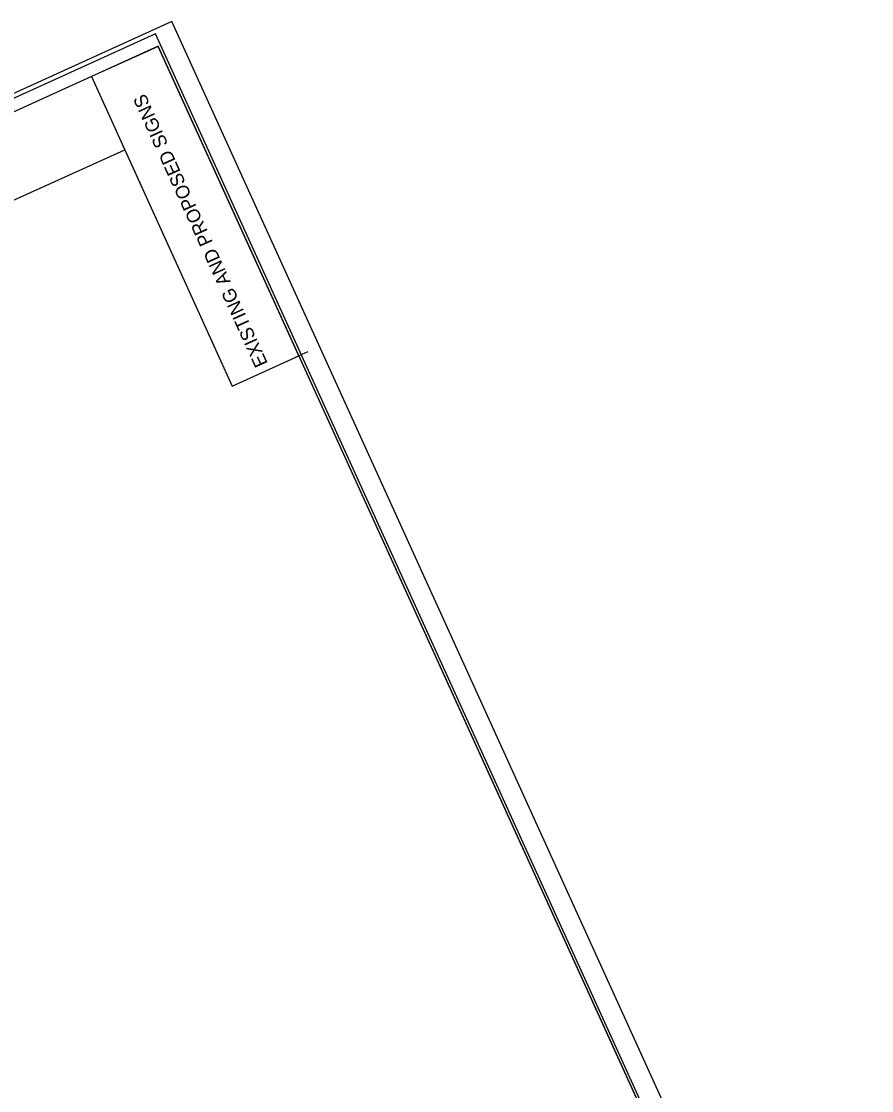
# Model space of a CAD drawing. Extents: x 2096093 to 2099001, y 683546 to 685907.
# Drawn here: x 2098154 to 2099001, y 684843 to 685907 of the extents above; entities that cross this region are included whole.
import ezdxf

# ---------------------------------------------------------------- set-up
doc = ezdxf.new("R2010")
doc.units = 0
for name, color, linetype in [('Default', 7, 'Continuous'), ('Old_Level_10', 7, 'Continuous'), ('Scratch_Level_0', 7, 'Continuous'), ('Scratch_Level_4', 7, 'Continuous'), ('Sheet Layout Plan Border', 7, 'Continuous'), ('Sheet Plan CELL', 7, 'Continuous'), ('Sheet Plot Border Inside CELL', 7, 'Continuous'), ('Sheet Plot Border Outside CELL', 7, 'Continuous')]:
    doc.layers.add(name, color=color, linetype=linetype)

msp = doc.modelspace()

# ---------------------------------------------------------------- linework, layer by layer
at = {"layer": 'Old_Level_10'}
msp.add_lwpolyline([(2098430, 685574.3), (2098289.9, 685882.4), (2098223.6, 685852.3), (2098363.7, 685544.2)], close=True, dxfattribs=at)
msp.add_lwpolyline([(2098430, 685574.3), (2098289.9, 685882.4), (2098223.6, 685852.3), (2098363.7, 685544.2)], close=True, dxfattribs=at)
at = {"layer": 'Scratch_Level_0'}
msp.add_line((2098427.5, 685573.2), (2098439.3, 685578.6), dxfattribs=at)
at = {"layer": 'Scratch_Level_4'}
msp.add_lwpolyline([(2097576.7, 685472.3), (2098256.8, 685779.3), (2098363.7, 685544.2), (2098430.1, 685574.3), (2098911.1, 684517.1), (2097955.4, 684082.4), (2097417.2, 685265.5), (2097411.6, 685277.8), (2097412.4, 685278.2), (2097621.8, 685373.4)], close=True, dxfattribs=at)
at = {"layer": 'Sheet Layout Plan Border'}
msp.add_lwpolyline([(2097576.7, 685472.3), (2098256.8, 685779.3), (2098363.7, 685544.2), (2098430.1, 685574.3), (2098911.1, 684517.1), (2097955.4, 684082.4), (2097417.2, 685265.5), (2097411.6, 685277.8), (2097412.4, 685278.2), (2097621.8, 685373.4)], close=True, dxfattribs=at)
at = {"layer": 'Sheet Plan CELL'}
msp.add_lwpolyline([(2097334.3, 685447.8), (2097955.4, 684082.4), (2098911.1, 684517.1), (2098290.1, 685882.5)], close=True, dxfattribs=at)
msp.add_lwpolyline([(2097334.3, 685447.8), (2097955.4, 684082.4), (2098911.1, 684517.1), (2098290.1, 685882.5)], close=True, dxfattribs=at)
at = {"layer": 'Sheet Plot Border Inside CELL'}
msp.add_lwpolyline([(2098977, 684378.4), (2098287.2, 685894.9), (2097326.9, 685458.1), (2098016.6, 683941.6)], close=True, dxfattribs=at)
msp.add_lwpolyline([(2098977, 684378.4), (2098287.2, 685894.9), (2097326.9, 685458.1), (2098016.6, 683941.6)], close=True, dxfattribs=at)
at = {"layer": 'Sheet Plot Border Outside CELL'}
msp.add_lwpolyline([(2099000.6, 684374.9), (2098303.6, 685907.3), (2097306.8, 685454), (2098003.8, 683921.5)], close=True, dxfattribs=at)
msp.add_lwpolyline([(2099000.6, 684374.9), (2098303.6, 685907.3), (2097306.8, 685454), (2098003.8, 683921.5)], close=True, dxfattribs=at)

# ---------------------------------------------------------------- texts
at = {"layer": 'Default'}
msp.add_text('EXISTING AND PROPOSED SIGNS', height=13.5, rotation=114.458, dxfattribs=at).set_placement((2098399.4, 685566.8))

doc.saveas('drawing.dxf')
